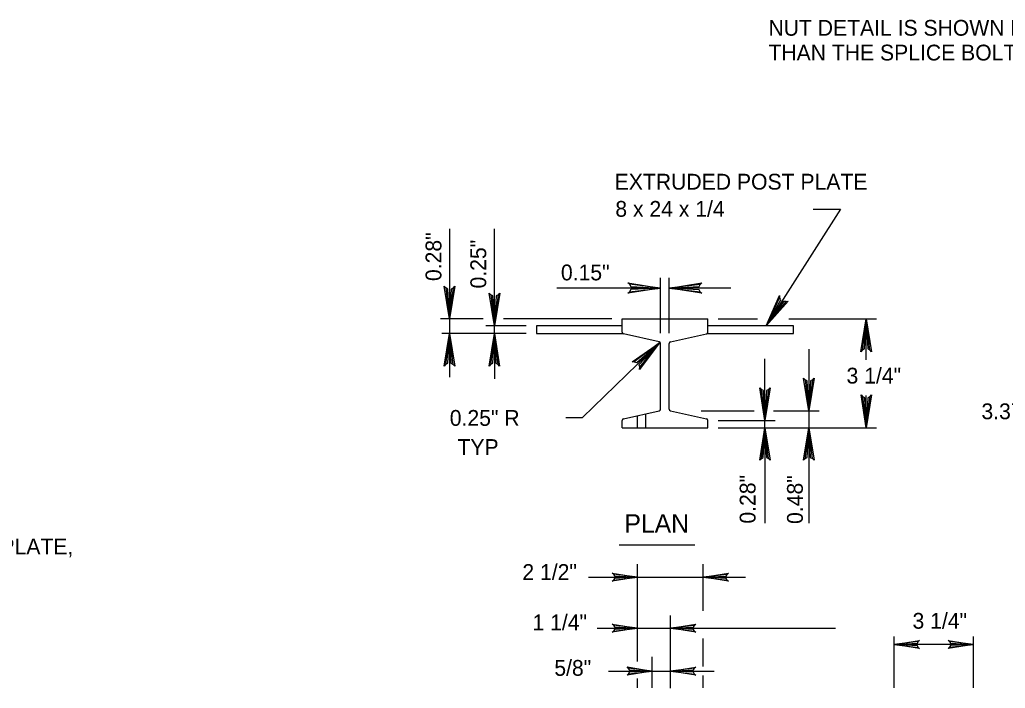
# Model space of a CAD drawing. Extents: x 637628 to 640188, y 298266 to 300751.
# Drawn here: x 638647.9 to 638834.9, y 299196.3 to 299323.2 of the extents above; entities that cross this region are included whole.
import ezdxf

# ---------------------------------------------------------------- set-up
doc = ezdxf.new("R2010")
doc.units = 0
for name, color, linetype in [('1', 7, 'Continuous'), ('2', 7, 'Continuous'), ('3', 7, 'Continuous')]:
    doc.layers.add(name, color=color, linetype=linetype)

msp = doc.modelspace()

# ---------------------------------------------------------------- linework, layer by layer
at = {"layer": '2'}
for p, q in [((638803.61, 299287.24), (638789.51, 299265.09)), ((638798.43, 299287.24), (638803.61, 299287.24)), ((638729.41, 299283.48), (638729.41, 299266.38)), ((638737.94, 299263.64), (638737.94, 299283.48)), ((638769.48, 299263.68), (638769.48, 299274.2)), ((638771.11, 299263.68), (638771.11, 299274.2)), ((638769.48, 299272.25), (638749.79, 299272.25)), ((638782.81, 299272.25), (638771.11, 299272.25)), ((638735.82, 299266.38), (638727.71, 299266.38)), ((638760.22, 299266.38), (638739.69, 299266.38)), ((638762.17, 299266.38), (638778.42, 299266.38)), ((638762.17, 299263.88), (638762.17, 299266.38)), ((638778.42, 299263.88), (638778.42, 299266.38)), ((638780.37, 299266.38), (638787.86, 299266.38)), ((638793.78, 299266.38), (638810.45, 299266.38)), ((638808.5, 299258.65), (638808.5, 299266.38)), ((638743.97, 299263.64), (638727.97, 299263.64)), ((638743.97, 299263.64), (638733.68, 299263.64)), ((638743.97, 299265.09), (638736.34, 299265.09)), ((638762.16, 299265.09), (638745.92, 299265.09)), ((638745.92, 299265.09), (638745.92, 299263.64)), ((638745.92, 299263.64), (638762.26, 299263.64)), ((638769.23, 299262.05), (638762.42, 299263.56)), ((638771.36, 299262.05), (638778.17, 299263.56)), ((638778.31, 299263.64), (638794.67, 299263.64)), ((638794.67, 299265.09), (638778.43, 299265.09)), ((638794.67, 299263.64), (638794.67, 299265.09)), ((638769.48, 299249.25), (638769.48, 299261.73)), ((638771.11, 299249.25), (638771.11, 299261.73)), ((638797.6, 299260.64), (638797.6, 299248.94)), ((638789.28, 299245.74), (638789.28, 299258.81)), ((638808.5, 299245.74), (638808.5, 299251.87)), ((638762.42, 299247.42), (638769.23, 299248.94)), ((638771.36, 299248.94), (638778.17, 299247.42)), ((638777.17, 299248.94), (638787.21, 299248.94)), ((638790.88, 299248.94), (638799.55, 299248.94)), ((638762.17, 299245.74), (638762.17, 299247.11)), ((638765.01, 299248), (638765.01, 299245.74)), ((638766.64, 299248.36), (638766.64, 299245.74)), ((638778.42, 299245.74), (638778.42, 299247.11)), ((638780.37, 299247.11), (638791.23, 299247.11)), ((638762.17, 299245.74), (638778.42, 299245.74)), ((638780.37, 299245.74), (638791.23, 299245.74)), ((638780.37, 299245.74), (638799.55, 299245.74)), ((638780.37, 299245.74), (638810.45, 299245.74)), ((638765.08, 299201.33), (638765.08, 299219.85)), ((638777.58, 299210.97), (638777.58, 299219.85)), ((638755.78, 299217.35), (638765.08, 299217.35)), ((638765.08, 299217.35), (638785.59, 299217.35)), ((638771.37, 299196.26), (638771.37, 299210.09)), ((638757.42, 299207.66), (638765.08, 299207.66)), ((638765.08, 299207.66), (638802.67, 299207.66)), ((638777.58, 299200.38), (638777.58, 299205.71)), ((638813.83, 299196.32), (638813.83, 299206.09)), ((638828.83, 299196.32), (638828.83, 299206.09)), ((638828.83, 299204.59), (638813.83, 299204.59)), ((638767.89, 299196.32), (638767.89, 299202.2)), ((638759.59, 299199.54), (638767.89, 299199.54)), ((638765.08, 299196.32), (638765.08, 299198.11)), ((638767.89, 299199.54), (638779.67, 299199.54)), ((638777.58, 299196.32), (638777.58, 299198.68))]:
    msp.add_line(p, q, dxfattribs=at)
for points in [[(638763.58, 299272.99), (638763.8, 299272.56), (638769.48, 299272.25), (638763.58, 299272.99), (638763.28, 299273.25), (638769.48, 299272.25), (638763.8, 299271.97), (638763.6, 299271.54), (638769.48, 299272.25), (638763.28, 299271.26), (638763.6, 299271.54)], [(638777.01, 299271.51), (638776.79, 299271.93), (638771.11, 299272.25), (638777.01, 299271.51), (638777.31, 299271.25), (638771.11, 299272.25), (638776.79, 299272.53), (638776.99, 299272.95), (638771.11, 299272.25), (638777.31, 299273.23), (638776.99, 299272.95)], [(638730.16, 299272.28), (638729.73, 299272.06), (638729.41, 299266.38), (638730.16, 299272.28), (638730.42, 299272.59), (638729.41, 299266.38), (638729.13, 299272.06), (638728.71, 299272.27), (638729.41, 299266.38), (638728.43, 299272.59), (638728.71, 299272.27)], [(638738.69, 299270.99), (638738.26, 299270.77), (638737.94, 299265.09), (638738.69, 299270.99), (638738.94, 299271.29), (638737.94, 299265.09), (638737.66, 299270.77), (638737.24, 299270.97), (638737.94, 299265.09), (638736.96, 299271.29), (638737.24, 299270.97)], [(638793.3, 299269.67), (638792.82, 299269.72), (638789.51, 299265.09), (638793.3, 299269.67), (638793.68, 299269.79), (638789.51, 299265.09), (638792.32, 299270.03), (638792.07, 299270.43), (638789.51, 299265.09), (638792.01, 299270.85), (638792.07, 299270.43)], [(638729.41, 299266.38), (638729.41, 299255.3)], [(638807.75, 299260.48), (638808.18, 299260.7), (638808.5, 299266.38), (638807.75, 299260.48), (638807.5, 299260.17), (638808.5, 299266.38), (638808.78, 299260.7), (638809.2, 299260.49), (638808.5, 299266.38), (638809.48, 299260.17), (638809.2, 299260.49)], [(638728.67, 299257.74), (638729.1, 299257.96), (638729.41, 299263.64), (638728.67, 299257.74), (638728.41, 299257.43), (638729.41, 299263.64), (638729.7, 299257.96), (638730.12, 299257.75), (638729.41, 299263.64), (638730.4, 299257.43), (638730.12, 299257.75)], [(638737.21, 299257.74), (638737.63, 299257.96), (638737.94, 299263.64), (638737.21, 299257.74), (638736.95, 299257.43), (638737.94, 299263.64), (638738.23, 299257.96), (638738.65, 299257.75), (638737.94, 299263.64), (638738.93, 299257.43), (638738.65, 299257.75)], [(638737.94, 299263.64), (638737.94, 299255.04)], [(638751.47, 299247.68), (638754.67, 299247.68), (638769.24, 299261.85)], [(638764.49, 299258.26), (638764.94, 299258.11), (638769.24, 299261.85), (638764.49, 299258.26), (638764.09, 299258.24), (638769.24, 299261.85), (638765.36, 299257.69), (638765.51, 299257.24), (638769.24, 299261.85), (638765.48, 299256.81), (638765.51, 299257.24)], [(638798.34, 299254.84), (638797.91, 299254.62), (638797.6, 299248.94), (638798.34, 299254.84), (638798.6, 299255.14), (638797.6, 299248.94), (638797.32, 299254.61), (638796.9, 299254.82), (638797.6, 299248.94), (638796.61, 299255.14), (638796.9, 299254.82)], [(638790.02, 299253.01), (638789.59, 299252.79), (638789.28, 299247.11), (638790.02, 299253.01), (638790.28, 299253.31), (638789.28, 299247.11), (638789, 299252.79), (638788.57, 299252.99), (638789.28, 299247.11), (638788.29, 299253.31), (638788.57, 299252.99)], [(638809.24, 299251.65), (638808.81, 299251.43), (638808.5, 299245.74), (638809.24, 299251.65), (638809.5, 299251.95), (638808.5, 299245.74), (638808.21, 299251.42), (638807.79, 299251.63), (638808.5, 299245.74), (638807.51, 299251.95), (638807.79, 299251.63)], [(638797.6, 299248.94), (638797.6, 299227.63)], [(638788.54, 299239.84), (638788.96, 299240.06), (638789.28, 299245.74), (638788.54, 299239.84), (638788.28, 299239.54), (638789.28, 299245.74), (638789.56, 299240.06), (638789.98, 299239.86), (638789.28, 299245.74), (638790.26, 299239.54), (638789.98, 299239.86)], [(638789.28, 299245.74), (638789.28, 299227.63)], [(638796.86, 299239.84), (638797.29, 299240.06), (638797.6, 299245.74), (638796.86, 299239.84), (638796.6, 299239.54), (638797.6, 299245.74), (638797.88, 299240.06), (638798.3, 299239.86), (638797.6, 299245.74), (638798.59, 299239.54), (638798.3, 299239.86)], [(638760.54, 299217.92), (638760.71, 299217.59), (638765.08, 299217.35), (638760.54, 299217.92), (638760.3, 299218.12), (638765.08, 299217.35), (638760.71, 299217.13), (638760.55, 299216.81), (638765.08, 299217.35), (638760.3, 299216.59), (638760.55, 299216.81)], [(638782.12, 299216.78), (638781.95, 299217.11), (638777.58, 299217.35), (638782.12, 299216.78), (638782.35, 299216.58), (638777.58, 299217.35), (638781.95, 299217.56), (638782.11, 299217.89), (638777.58, 299217.35), (638782.35, 299218.1), (638782.11, 299217.89)], [(638760.54, 299208.23), (638760.71, 299207.9), (638765.08, 299207.66), (638760.54, 299208.23), (638760.3, 299208.43), (638765.08, 299207.66), (638760.71, 299207.45), (638760.55, 299207.12), (638765.08, 299207.66), (638760.3, 299206.9), (638760.55, 299207.12)], [(638775.91, 299207.09), (638775.74, 299207.42), (638771.37, 299207.66), (638775.91, 299207.09), (638776.14, 299206.89), (638771.37, 299207.66), (638775.74, 299207.88), (638775.9, 299208.2), (638771.37, 299207.66), (638776.14, 299208.42), (638775.9, 299208.2)], [(638818.37, 299204.02), (638818.2, 299204.35), (638813.83, 299204.59), (638818.37, 299204.02), (638818.6, 299203.82), (638813.83, 299204.59), (638818.2, 299204.81), (638818.36, 299205.14), (638813.83, 299204.59), (638818.6, 299205.35), (638818.36, 299205.14)], [(638824.29, 299205.16), (638824.46, 299204.84), (638828.83, 299204.59), (638824.29, 299205.16), (638824.05, 299205.36), (638828.83, 299204.59), (638824.46, 299204.38), (638824.3, 299204.05), (638828.83, 299204.59), (638824.05, 299203.84), (638824.3, 299204.05)], [(638763.35, 299200.11), (638763.52, 299199.78), (638767.89, 299199.54), (638763.35, 299200.11), (638763.12, 299200.31), (638767.89, 299199.54), (638763.52, 299199.32), (638763.36, 299199), (638767.89, 299199.54), (638763.12, 299198.78), (638763.36, 299199)], [(638775.91, 299198.97), (638775.74, 299199.3), (638771.37, 299199.54), (638775.91, 299198.97), (638776.14, 299198.77), (638771.37, 299199.54), (638775.74, 299199.76), (638775.9, 299200.08), (638771.37, 299199.54), (638776.14, 299200.3), (638775.9, 299200.08)]]:
    msp.add_lwpolyline(points, dxfattribs=at)
for centre, start, end in [((638762.5, 299263.88), 180, 257.4712), ((638778.1, 299263.88), 282.5288, 0), ((638769.16, 299261.73), 0, 77.4712), ((638771.43, 299261.73), 102.5288, 180), ((638769.16, 299249.25), 282.5288, 0), ((638771.43, 299249.25), 180, 257.4712), ((638762.5, 299247.11), 102.5288, 180), ((638778.1, 299247.11), 0, 77.4712)]:
    msp.add_arc(centre, 0.325, start, end, dxfattribs=at)
at = {"layer": '3'}
msp.add_line((638761.59, 299223.49), (638775.98, 299223.49), dxfattribs=at)

# ---------------------------------------------------------------- texts
at = {"layer": '1'}
for s, p in [('NUT DETAIL IS SHOWN PROPORTIONALLY LARGER', (638789.94, 299320.16)), ('THAN THE SPLICE BOLT DETAIL FOR CLARITY.', (638789.94, 299315.46)), ('8 x 24 x 1/4', (638760.89, 299285.78)), ('3.375" +0.125"', (638830.36, 299247.35)), ('12 GAGE W-BEAM BACKUP PLATE,', (638590.71, 299221.69)), ('3 1/4"', (638817.28, 299207.57))]:
    msp.add_text(s, height=3, dxfattribs=at).set_placement(p)
at = {"layer": '3'}
for s, height, p in [('EXTRUDED POST PLATE', 3.003, (638760.76, 299290.94)), ('0.15"', 3.003, (638750.56, 299273.71)), ('3 1/4"', 3.003, (638804.76, 299254.12)), ('0.25" R', 3.003, (638729.47, 299246.09)), ('TYP', 3.003, (638730.93, 299240.56)), ('PLAN', 3.503, (638762.62, 299225.81)), ('2 1/2"', 3, (638743.25, 299216.83)), ('1 1/4"', 3, (638745.17, 299207.28)), ('5/8"', 3, (638749.31, 299198.63))]:
    msp.add_text(s, height=height, dxfattribs=at).set_placement(p)
for s, p in [('0.28"', (638727.88, 299273.58)), ('0.25"', (638736.38, 299272.17)), ('0.28"', (638787.49, 299227.53)), ('0.48"', (638796.47, 299227.46))]:
    msp.add_text(s, height=3.003, rotation=90, dxfattribs=at).set_placement(p)

doc.saveas('drawing.dxf')
